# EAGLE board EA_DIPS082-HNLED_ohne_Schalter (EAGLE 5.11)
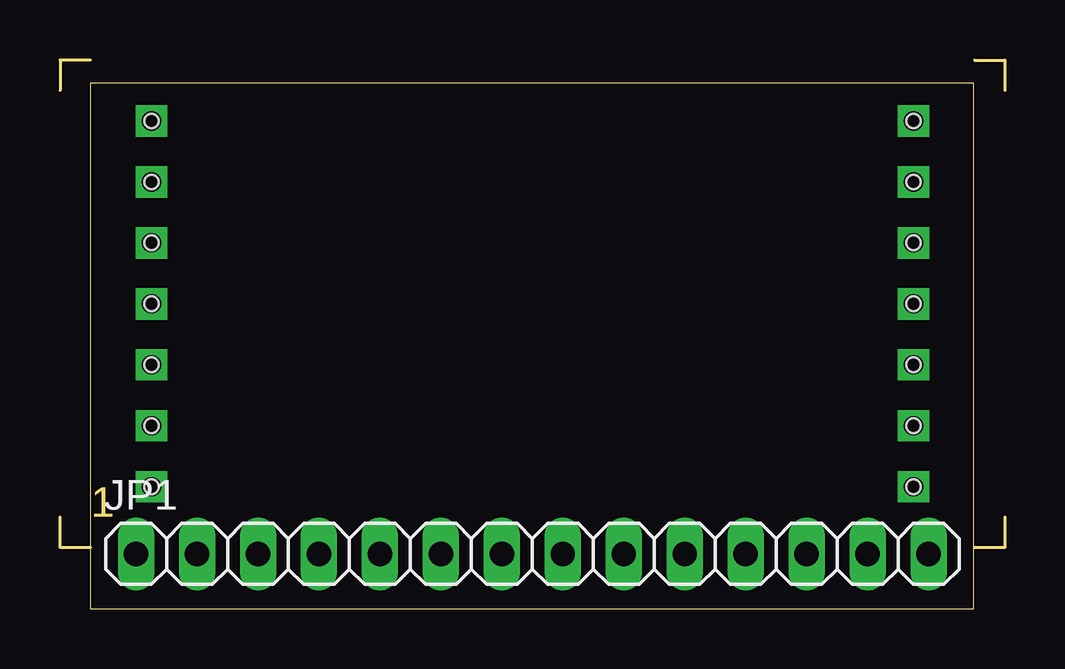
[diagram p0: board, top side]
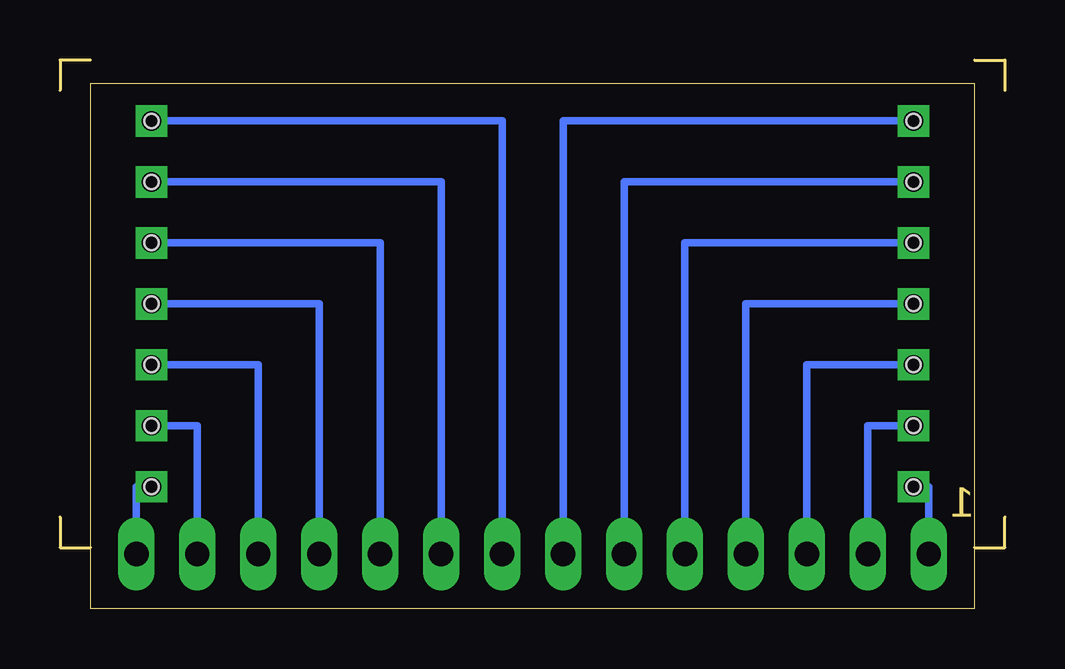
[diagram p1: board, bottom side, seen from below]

Size 39.37 x 22.86 mm. Coordinates in mm from the lower left corner, seen from the top.
Outline: 1.27,0 38.08,0 38.08,21.89 1.27,21.89 1.27,0
Copper layers (1*16): Top 0.035mm / dielectric 1.5mm / Bottom 0.035mm
Design rules "default": minimum track width 10mil, minimum drill 24mil, track to track 8mil, track to pad 8mil, pad to pad 8mil, via to via 8mil, smd to smd 8mil, copper to edge 40mil, drill to drill 8mil, minimum pad ring 10mil, minimum via ring 8mil, stop-mask expansion 4mil, vias tented up to drill 0mil, thermal gap 10mil

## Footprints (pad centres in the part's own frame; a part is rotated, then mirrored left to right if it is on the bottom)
1X14 = drill 1.016 long: 1 -16.51,0; 2 -13.97,0; 3 -11.43,0; 4 -8.89,0; 5 -6.35,0; 6 -3.81,0; 7 -1.27,0; 8 1.27,0; 9 3.81,0; 10 6.35,0; 11 8.89,0; 12 11.43,0; 13 13.97,0; 14 16.51,0
DIPS082 = drill 0.8 square: D0 0,6.35; D1 31.75,6.35; D2 31.75,3.81; D3 31.75,1.27; D4 31.75,-1.27; D5 31.75,-3.81; D6 31.75,-6.35; D7 31.75,-8.89; ENA 0,3.81; R/W 0,1.27; RS 0,-1.27; VDD 0,-6.35; VEE 0,-3.81; VSS 0,-8.89 | hole 0.6: 0,6.35; 0,3.81; 0,1.27; 0,-1.27; 0,-3.81; 0,-6.35; 0,-8.89; 31.75,-8.89; 31.75,-6.35; 31.75,-3.81; 31.75,-1.27; 31.75,1.27; 31.75,3.81; 31.75,6.35

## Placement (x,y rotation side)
JP1  [1X14]  19.68,2.28 0 top
U$1  DIPS082  [DIPS082]  3.81,13.97 0 top

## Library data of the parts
JP1 = pinhead
U$1 = dips082

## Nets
N$1: JP1.1 U$1.VSS
N$2: JP1.2 U$1.VDD
N$3: JP1.3 U$1.VEE
N$4: JP1.4 U$1.RS
N$5: JP1.5 U$1.R/W
N$6: JP1.6 U$1.ENA
N$7: JP1.7 U$1.D0
N$8: JP1.8 U$1.D1
N$9: JP1.9 U$1.D2
N$10: JP1.10 U$1.D3
N$11: JP1.11 U$1.D4
N$12: JP1.12 U$1.D5
N$13: JP1.13 U$1.D6
N$14: JP1.14 U$1.D7

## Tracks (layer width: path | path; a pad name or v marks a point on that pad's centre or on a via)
N$1
  Bottom 0.305: U$1.VSS 3.17,5.08 JP1.1
N$2
  Bottom 0.305: U$1.VDD 5.71,7.62 JP1.2
N$3
  Bottom 0.305: U$1.VEE 8.25,10.16 JP1.3
N$4
  Bottom 0.305: U$1.RS 10.79,12.7 JP1.4
N$5
  Bottom 0.305: U$1.R/W 13.33,15.24 JP1.5
N$6
  Bottom 0.305: U$1.ENA 15.87,17.78 JP1.6
N$7
  Bottom 0.305: U$1.D0 18.41,20.32 JP1.7
N$8
  Bottom 0.305: U$1.D1 20.95,20.32 JP1.8
N$9
  Bottom 0.305: U$1.D2 23.49,17.78 JP1.9
N$10
  Bottom 0.305: U$1.D3 26.03,15.24 JP1.10
N$11
  Bottom 0.305: U$1.D4 28.57,12.7 JP1.11
N$12
  Bottom 0.305: U$1.D5 31.11,10.16 JP1.12
N$13
  Bottom 0.305: U$1.D6 33.65,7.62 JP1.13
N$14
  Bottom 0.305: U$1.D7 36.19,5.08 JP1.14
